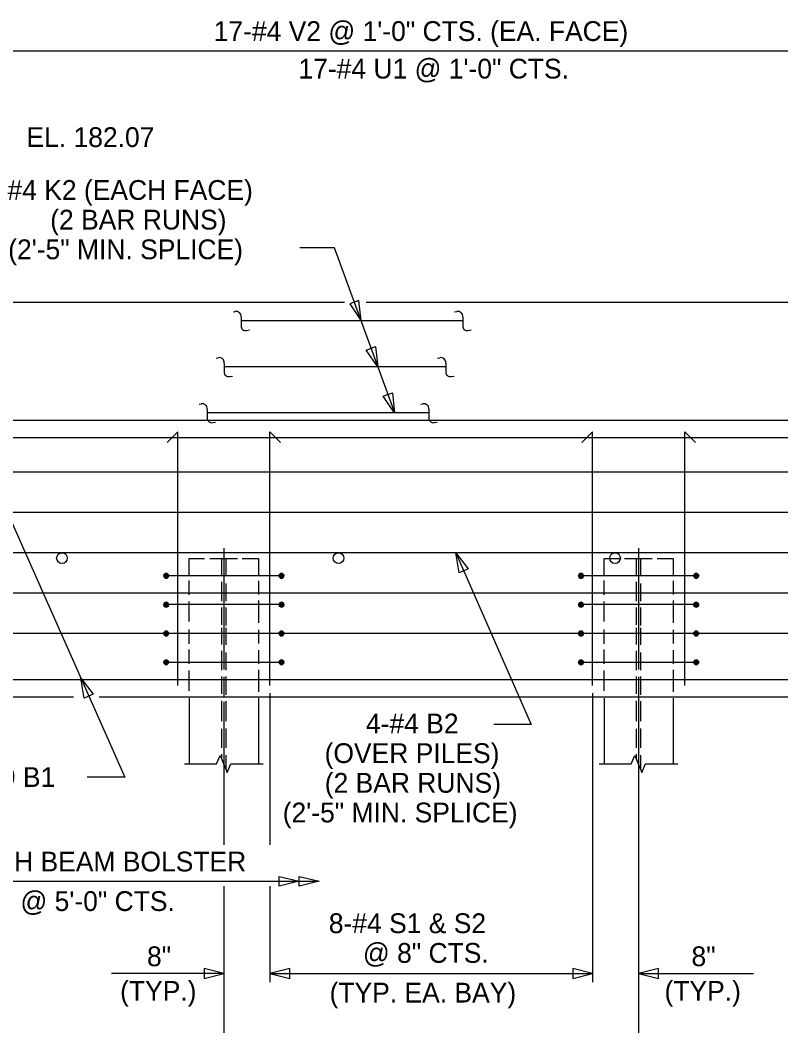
# Model space of a CAD drawing. Extents: x -41 to 191, y -168 to 6.
# Drawn here: x 132.62 to 143.62, y -41 to -26.46 of the extents above; entities that cross this region are included whole.
import ezdxf

# ---------------------------------------------------------------- set-up
doc = ezdxf.new("R2010")
doc.units = 0
for name, color, linetype in [('Arrowhead Terminators CELL', 7, 'Continuous'), ('Dimension Lines', 7, 'Continuous'), ('Mis Object Lines', 7, 'Continuous'), ('Rebar Lines', 7, 'Continuous'), ('Rebar Lines CELL', 7, 'Continuous'), ('Text', 7, 'Continuous')]:
    doc.layers.add(name, color=color, linetype=linetype)

msp = doc.modelspace()

# ---------------------------------------------------------------- linework, layer by layer
at = {"layer": 'Arrowhead Terminators CELL'}
for p, q in [((135.699, -30.684), (135.73, -30.678)), ((135.699, -30.684), (135.73, -30.678)), ((138.904, -30.684), (138.935, -30.678)), ((135.817, -30.757), (135.817, -30.883)), ((135.817, -30.757), (135.817, -30.883)), ((139.022, -30.757), (139.022, -30.883)), ((135.895, -30.95), (135.936, -30.944)), ((135.895, -30.95), (135.936, -30.944)), ((139.1, -30.95), (139.142, -30.944)), ((135.454, -31.35), (135.485, -31.345)), ((135.454, -31.35), (135.485, -31.345)), ((138.659, -31.35), (138.69, -31.345)), ((138.659, -31.35), (138.69, -31.345)), ((135.572, -31.423), (135.572, -31.55)), ((135.572, -31.423), (135.572, -31.55)), ((138.777, -31.423), (138.777, -31.55)), ((138.777, -31.423), (138.777, -31.55)), ((135.65, -31.616), (135.692, -31.611)), ((135.65, -31.616), (135.692, -31.611)), ((138.855, -31.616), (138.897, -31.611)), ((138.855, -31.616), (138.897, -31.611)), ((135.209, -32.017), (135.24, -32.012)), ((135.209, -32.017), (135.24, -32.012)), ((135.327, -32.09), (135.327, -32.216)), ((135.327, -32.09), (135.327, -32.216)), ((138.414, -32.017), (138.445, -32.012)), ((138.414, -32.017), (138.445, -32.012)), ((138.532, -32.09), (138.532, -32.216)), ((138.532, -32.09), (138.532, -32.216)), ((135.405, -32.283), (135.447, -32.278)), ((135.405, -32.283), (135.447, -32.278)), ((138.61, -32.283), (138.652, -32.278)), ((138.61, -32.283), (138.652, -32.278))]:
    msp.add_line(p, q, dxfattribs=at)
for points in [[(137.553, -30.811), (137.521, -30.518), (137.387, -30.567)], [(137.792, -31.478), (137.626, -31.234), (137.76, -31.184)], [(138.037, -32.144), (137.871, -31.9), (138.005, -31.851)], [(138.922, -34.165), (139.103, -34.398), (138.971, -34.456)], [(133.496, -35.978), (133.677, -36.211), (133.546, -36.269)], [(136.655, -38.915), (136.366, -38.987), (136.366, -38.843)], [(136.944, -38.915), (136.655, -38.987), (136.655, -38.843)], [(135.566, -40.249), (135.28, -40.177), (135.28, -40.32)], [(136.233, -40.249), (136.519, -40.32), (136.519, -40.177)], [(140.9, -40.249), (140.613, -40.177), (140.613, -40.32)], [(141.566, -40.249), (141.853, -40.32), (141.853, -40.177)]]:
    msp.add_lwpolyline(points, close=True, dxfattribs=at)
for centre, radius, start, end in [((135.746, -30.748), 0.0712, 353.437, 103.2358), ((135.746, -30.748), 0.0712, 353.437, 103.2358), ((138.951, -30.748), 0.0712, 353.437, 103.2358), ((135.879, -30.888), 0.0632, 175.8818, 284.1674), ((135.879, -30.888), 0.0632, 175.8818, 284.1674), ((139.085, -30.888), 0.0632, 175.8818, 284.1674), ((135.501, -31.415), 0.0712, 353.437, 103.2358), ((135.501, -31.415), 0.0712, 353.437, 103.2358), ((138.706, -31.415), 0.0712, 353.437, 103.2358), ((138.706, -31.415), 0.0712, 353.437, 103.2358), ((135.634, -31.555), 0.0632, 175.8818, 284.1674), ((135.634, -31.555), 0.0632, 175.8818, 284.1674), ((138.84, -31.555), 0.0632, 175.8818, 284.1674), ((138.84, -31.555), 0.0632, 175.8818, 284.1674), ((135.256, -32.082), 0.0712, 353.437, 103.2358), ((135.256, -32.082), 0.0712, 353.437, 103.2358), ((138.461, -32.082), 0.0712, 353.437, 103.2358), ((138.461, -32.082), 0.0712, 353.437, 103.2358), ((135.389, -32.221), 0.0632, 175.8818, 284.1674), ((135.389, -32.221), 0.0632, 175.8818, 284.1674), ((138.595, -32.221), 0.0632, 175.8818, 284.1674), ((138.595, -32.221), 0.0632, 175.8818, 284.1674)]:
    msp.add_arc(centre, radius, start, end, dxfattribs=at)
at = {"layer": 'Dimension Lines'}
for p, q in [((131.375, -26.909), (147.448, -26.909)), ((136.233, -36.195), (136.233, -38.388)), ((140.9, -36.195), (140.9, -40.374)), ((141.566, -36.249), (141.566, -42.558)), ((135.566, -37.524), (135.566, -38.388)), ((131.03, -38.915), (136.944, -38.915)), ((135.566, -38.987), (135.566, -42.873)), ((136.233, -38.987), (136.233, -40.374)), ((135.566, -40.249), (133.941, -40.249)), ((136.233, -40.249), (140.9, -40.249)), ((141.566, -40.249), (143.228, -40.249))]:
    msp.add_line(p, q, dxfattribs=at)
for points in [[(138.042, -32.144), (137.166, -29.758), (136.666, -29.758)], [(131.952, -32.5), (134.132, -37.41), (133.591, -37.41)], [(138.922, -34.165), (140.014, -36.648), (139.473, -36.648)]]:
    msp.add_lwpolyline(points, dxfattribs=at)
at = {"layer": 'Mis Object Lines'}
for p, q in [((130.841, -30.54), (137.314, -30.54)), ((137.623, -30.54), (164.491, -30.54)), ((131.167, -32.249), (147.948, -32.249)), ((126.948, -36.249), (133.392, -36.249)), ((133.764, -36.249), (168.185, -36.249))]:
    msp.add_line(p, q, dxfattribs=at)
at = {"layer": 'Rebar Lines'}
for p, q in [((139.023, -30.811), (135.818, -30.811)), ((138.778, -31.478), (135.573, -31.478)), ((138.534, -32.144), (135.328, -32.144)), ((134.9, -32.415), (134.746, -32.569)), ((134.9, -36.082), (134.9, -32.415)), ((136.233, -32.415), (136.387, -32.569)), ((136.233, -36.082), (136.233, -32.415)), ((140.9, -32.415), (140.746, -32.569)), ((140.9, -36.082), (140.9, -32.415)), ((142.233, -32.415), (142.387, -32.569)), ((142.233, -36.082), (142.233, -32.415)), ((127.69, -32.5), (166.732, -32.5)), ((149.156, -32.999), (127.115, -32.999)), ((149.156, -33.582), (127.115, -33.582)), ((149.156, -34.165), (127.115, -34.165)), ((135.566, -34.097), (135.566, -35.854)), ((141.566, -34.097), (141.566, -35.854)), ((135.535, -34.491), (135.535, -34.249)), ((135.598, -34.497), (135.598, -34.249)), ((141.535, -34.491), (141.535, -34.249)), ((141.598, -34.497), (141.598, -34.249)), ((135.535, -34.863), (135.535, -34.584)), ((141.535, -34.863), (141.535, -34.584)), ((149.156, -34.749), (127.115, -34.749)), ((135.598, -34.863), (135.598, -34.607)), ((141.598, -34.863), (141.598, -34.607)), ((135.535, -35.206), (135.535, -34.956)), ((135.598, -35.217), (135.598, -34.956)), ((141.535, -35.206), (141.535, -34.956)), ((141.598, -35.217), (141.598, -34.956)), ((149.156, -35.332), (127.115, -35.332)), ((135.535, -35.491), (135.535, -35.249)), ((135.598, -35.497), (135.598, -35.249)), ((141.535, -35.491), (141.535, -35.249)), ((141.598, -35.497), (141.598, -35.249)), ((135.535, -35.863), (135.535, -35.584)), ((135.598, -35.863), (135.598, -35.607)), ((141.535, -35.863), (141.535, -35.584)), ((141.598, -35.863), (141.598, -35.607)), ((127.69, -35.999), (166.825, -35.999)), ((135.535, -36.206), (135.535, -35.956)), ((135.566, -35.958), (135.566, -36.249)), ((135.598, -36.217), (135.598, -35.956)), ((141.535, -36.206), (141.535, -35.956)), ((141.566, -35.958), (141.566, -36.249)), ((141.598, -36.217), (141.598, -35.956)), ((135.066, -36.266), (135.066, -37.218)), ((135.535, -36.601), (135.535, -36.304)), ((135.566, -36.318), (135.566, -37.524)), ((135.598, -36.601), (135.598, -36.31)), ((136.067, -36.266), (136.067, -37.218)), ((141.066, -36.266), (141.066, -37.218)), ((141.535, -36.601), (141.535, -36.304)), ((141.566, -36.318), (141.566, -37.524)), ((141.598, -36.601), (141.598, -36.31)), ((142.067, -36.266), (142.067, -37.218)), ((135.535, -36.984), (135.535, -36.711)), ((135.598, -36.984), (135.598, -36.705)), ((141.535, -36.984), (141.535, -36.711)), ((141.598, -36.984), (141.598, -36.705)), ((135.535, -37.152), (135.535, -37.077)), ((141.535, -37.152), (141.535, -37.077)), ((135.598, -37.301), (135.598, -37.089)), ((141.598, -37.301), (141.598, -37.089))]:
    msp.add_line(p, q, dxfattribs=at)
for points in [[(135.066, -34.482), (135.066, -34.249), (135.289, -34.249)], [(135.364, -34.249), (135.764, -34.249)], [(135.833, -34.249), (136.066, -34.249), (136.066, -34.495)], [(141.066, -34.482), (141.066, -34.249), (141.289, -34.249)], [(141.364, -34.249), (141.764, -34.249)], [(141.833, -34.249), (142.066, -34.249), (142.066, -34.495)], [(135.066, -34.773), (135.066, -34.565)], [(136.066, -34.571), (136.066, -34.77)], [(141.066, -34.773), (141.066, -34.565)], [(142.066, -34.571), (142.066, -34.77)], [(135.066, -35.16), (135.066, -34.868)], [(136.066, -34.855), (136.066, -35.176)], [(141.066, -35.16), (141.066, -34.868)], [(142.066, -34.855), (142.066, -35.176)], [(135.066, -35.482), (135.066, -35.274)], [(136.066, -35.28), (136.066, -35.479)], [(141.066, -35.482), (141.066, -35.274)], [(142.066, -35.28), (142.066, -35.479)], [(135.066, -35.773), (135.066, -35.565)], [(136.066, -35.571), (136.066, -35.77)], [(141.066, -35.773), (141.066, -35.565)], [(142.066, -35.571), (142.066, -35.77)], [(135.066, -36.16), (135.066, -35.868)], [(136.066, -35.855), (136.066, -36.176)], [(141.066, -36.16), (141.066, -35.868)], [(142.066, -35.855), (142.066, -36.176)], [(134.996, -37.218), (135.458, -37.218), (135.513, -37.098), (135.615, -37.343), (135.667, -37.218), (136.133, -37.218)], [(140.996, -37.218), (141.458, -37.218), (141.513, -37.098), (141.615, -37.343), (141.667, -37.218), (142.133, -37.218)]]:
    msp.add_lwpolyline(points, dxfattribs=at)
at = {"layer": 'Rebar Lines CELL'}
for p, q in [((136.4, -34.499), (134.733, -34.499)), ((142.4, -34.499), (140.733, -34.499)), ((136.4, -34.915), (134.733, -34.915)), ((142.4, -34.915), (140.733, -34.915)), ((136.4, -35.332), (134.733, -35.332)), ((142.4, -35.332), (140.733, -35.332)), ((136.4, -35.749), (134.733, -35.749)), ((142.4, -35.749), (140.733, -35.749))]:
    msp.add_line(p, q, dxfattribs=at)
for points in [[(134.733, -34.463), (134.72, -34.466), (134.708, -34.474), (134.7, -34.485), (134.698, -34.499), (134.7, -34.512), (134.708, -34.523), (134.72, -34.531), (134.733, -34.534), (134.746, -34.531), (134.758, -34.523), (134.766, -34.512), (134.768, -34.499), (134.766, -34.485), (134.758, -34.474), (134.747, -34.466), (134.733, -34.463), (134.733, -34.499), (134.733, -34.534), (134.72, -34.531), (134.733, -34.499), (134.708, -34.523), (134.7, -34.512), (134.733, -34.499), (134.698, -34.499), (134.7, -34.485), (134.733, -34.499), (134.708, -34.474), (134.72, -34.466), (134.733, -34.499), (134.747, -34.466), (134.758, -34.474), (134.733, -34.499), (134.766, -34.485), (134.768, -34.499), (134.733, -34.499), (134.766, -34.512), (134.758, -34.523), (134.733, -34.499), (134.746, -34.531)], [(136.4, -34.463), (136.386, -34.466), (136.375, -34.474), (136.367, -34.485), (136.365, -34.499), (136.367, -34.512), (136.375, -34.523), (136.386, -34.531), (136.4, -34.534), (136.413, -34.531), (136.425, -34.523), (136.432, -34.512), (136.435, -34.499), (136.432, -34.485), (136.425, -34.474), (136.413, -34.466), (136.4, -34.463), (136.4, -34.499), (136.4, -34.534), (136.386, -34.531), (136.4, -34.499), (136.375, -34.523), (136.367, -34.512), (136.4, -34.499), (136.365, -34.499), (136.367, -34.485), (136.4, -34.499), (136.375, -34.474), (136.386, -34.466), (136.4, -34.499), (136.413, -34.466), (136.425, -34.474), (136.4, -34.499), (136.432, -34.485), (136.435, -34.499), (136.4, -34.499), (136.432, -34.512), (136.425, -34.523), (136.4, -34.499), (136.413, -34.531)], [(140.733, -34.463), (140.72, -34.466), (140.708, -34.474), (140.7, -34.485), (140.698, -34.499), (140.7, -34.512), (140.708, -34.523), (140.72, -34.531), (140.733, -34.534), (140.746, -34.531), (140.758, -34.523), (140.766, -34.512), (140.768, -34.499), (140.766, -34.485), (140.758, -34.474), (140.747, -34.466), (140.733, -34.463), (140.733, -34.499), (140.733, -34.534), (140.72, -34.531), (140.733, -34.499), (140.708, -34.523), (140.7, -34.512), (140.733, -34.499), (140.698, -34.499), (140.7, -34.485), (140.733, -34.499), (140.708, -34.474), (140.72, -34.466), (140.733, -34.499), (140.747, -34.466), (140.758, -34.474), (140.733, -34.499), (140.766, -34.485), (140.768, -34.499), (140.733, -34.499), (140.766, -34.512), (140.758, -34.523), (140.733, -34.499), (140.746, -34.531)], [(142.4, -34.463), (142.386, -34.466), (142.375, -34.474), (142.367, -34.485), (142.365, -34.499), (142.367, -34.512), (142.375, -34.523), (142.386, -34.531), (142.4, -34.534), (142.413, -34.531), (142.425, -34.523), (142.432, -34.512), (142.435, -34.499), (142.432, -34.485), (142.425, -34.474), (142.413, -34.466), (142.4, -34.463), (142.4, -34.499), (142.4, -34.534), (142.386, -34.531), (142.4, -34.499), (142.375, -34.523), (142.367, -34.512), (142.4, -34.499), (142.365, -34.499), (142.367, -34.485), (142.4, -34.499), (142.375, -34.474), (142.386, -34.466), (142.4, -34.499), (142.413, -34.466), (142.425, -34.474), (142.4, -34.499), (142.432, -34.485), (142.435, -34.499), (142.4, -34.499), (142.432, -34.512), (142.425, -34.523), (142.4, -34.499), (142.413, -34.531)], [(134.733, -34.88), (134.72, -34.883), (134.708, -34.89), (134.7, -34.902), (134.698, -34.915), (134.7, -34.929), (134.708, -34.94), (134.72, -34.948), (134.733, -34.95), (134.746, -34.948), (134.758, -34.94), (134.766, -34.929), (134.768, -34.915), (134.766, -34.902), (134.758, -34.89), (134.747, -34.883), (134.733, -34.88), (134.733, -34.915), (134.733, -34.95), (134.72, -34.948), (134.733, -34.915), (134.708, -34.94), (134.7, -34.929), (134.733, -34.915), (134.698, -34.915), (134.7, -34.902), (134.733, -34.915), (134.708, -34.89), (134.72, -34.883), (134.733, -34.915), (134.747, -34.883), (134.758, -34.89), (134.733, -34.915), (134.766, -34.902), (134.768, -34.915), (134.733, -34.915), (134.766, -34.929), (134.758, -34.94), (134.733, -34.915), (134.746, -34.948)], [(136.4, -34.88), (136.386, -34.883), (136.375, -34.89), (136.367, -34.902), (136.365, -34.915), (136.367, -34.929), (136.375, -34.94), (136.386, -34.948), (136.4, -34.95), (136.413, -34.948), (136.425, -34.94), (136.432, -34.929), (136.435, -34.915), (136.432, -34.902), (136.425, -34.89), (136.413, -34.883), (136.4, -34.88), (136.4, -34.915), (136.4, -34.95), (136.386, -34.948), (136.4, -34.915), (136.375, -34.94), (136.367, -34.929), (136.4, -34.915), (136.365, -34.915), (136.367, -34.902), (136.4, -34.915), (136.375, -34.89), (136.386, -34.883), (136.4, -34.915), (136.413, -34.883), (136.425, -34.89), (136.4, -34.915), (136.432, -34.902), (136.435, -34.915), (136.4, -34.915), (136.432, -34.929), (136.425, -34.94), (136.4, -34.915), (136.413, -34.948)], [(140.733, -34.88), (140.72, -34.883), (140.708, -34.89), (140.7, -34.902), (140.698, -34.915), (140.7, -34.929), (140.708, -34.94), (140.72, -34.948), (140.733, -34.95), (140.746, -34.948), (140.758, -34.94), (140.766, -34.929), (140.768, -34.915), (140.766, -34.902), (140.758, -34.89), (140.747, -34.883), (140.733, -34.88), (140.733, -34.915), (140.733, -34.95), (140.72, -34.948), (140.733, -34.915), (140.708, -34.94), (140.7, -34.929), (140.733, -34.915), (140.698, -34.915), (140.7, -34.902), (140.733, -34.915), (140.708, -34.89), (140.72, -34.883), (140.733, -34.915), (140.747, -34.883), (140.758, -34.89), (140.733, -34.915), (140.766, -34.902), (140.768, -34.915), (140.733, -34.915), (140.766, -34.929), (140.758, -34.94), (140.733, -34.915), (140.746, -34.948)], [(142.4, -34.88), (142.386, -34.883), (142.375, -34.89), (142.367, -34.902), (142.365, -34.915), (142.367, -34.929), (142.375, -34.94), (142.386, -34.948), (142.4, -34.95), (142.413, -34.948), (142.425, -34.94), (142.432, -34.929), (142.435, -34.915), (142.432, -34.902), (142.425, -34.89), (142.413, -34.883), (142.4, -34.88), (142.4, -34.915), (142.4, -34.95), (142.386, -34.948), (142.4, -34.915), (142.375, -34.94), (142.367, -34.929), (142.4, -34.915), (142.365, -34.915), (142.367, -34.902), (142.4, -34.915), (142.375, -34.89), (142.386, -34.883), (142.4, -34.915), (142.413, -34.883), (142.425, -34.89), (142.4, -34.915), (142.432, -34.902), (142.435, -34.915), (142.4, -34.915), (142.432, -34.929), (142.425, -34.94), (142.4, -34.915), (142.413, -34.948)], [(134.733, -35.297), (134.72, -35.299), (134.708, -35.307), (134.7, -35.318), (134.698, -35.332), (134.7, -35.345), (134.708, -35.357), (134.72, -35.364), (134.733, -35.367), (134.746, -35.364), (134.758, -35.357), (134.766, -35.345), (134.768, -35.332), (134.766, -35.318), (134.758, -35.307), (134.747, -35.299), (134.733, -35.297), (134.733, -35.332), (134.733, -35.367), (134.72, -35.364), (134.733, -35.332), (134.708, -35.357), (134.7, -35.345), (134.733, -35.332), (134.698, -35.332), (134.7, -35.318), (134.733, -35.332), (134.708, -35.307), (134.72, -35.299), (134.733, -35.332), (134.747, -35.299), (134.758, -35.307), (134.733, -35.332), (134.766, -35.318), (134.768, -35.332), (134.733, -35.332), (134.766, -35.345), (134.758, -35.357), (134.733, -35.332), (134.746, -35.364)], [(136.4, -35.297), (136.386, -35.299), (136.375, -35.307), (136.367, -35.318), (136.365, -35.332), (136.367, -35.345), (136.375, -35.357), (136.386, -35.364), (136.4, -35.367), (136.413, -35.364), (136.425, -35.357), (136.432, -35.345), (136.435, -35.332), (136.432, -35.318), (136.425, -35.307), (136.413, -35.299), (136.4, -35.297), (136.4, -35.332), (136.4, -35.367), (136.386, -35.364), (136.4, -35.332), (136.375, -35.357), (136.367, -35.345), (136.4, -35.332), (136.365, -35.332), (136.367, -35.318), (136.4, -35.332), (136.375, -35.307), (136.386, -35.299), (136.4, -35.332), (136.413, -35.299), (136.425, -35.307), (136.4, -35.332), (136.432, -35.318), (136.435, -35.332), (136.4, -35.332), (136.432, -35.345), (136.425, -35.357), (136.4, -35.332), (136.413, -35.364)], [(140.733, -35.297), (140.72, -35.299), (140.708, -35.307), (140.7, -35.318), (140.698, -35.332), (140.7, -35.345), (140.708, -35.357), (140.72, -35.364), (140.733, -35.367), (140.746, -35.364), (140.758, -35.357), (140.766, -35.345), (140.768, -35.332), (140.766, -35.318), (140.758, -35.307), (140.747, -35.299), (140.733, -35.297), (140.733, -35.332), (140.733, -35.367), (140.72, -35.364), (140.733, -35.332), (140.708, -35.357), (140.7, -35.345), (140.733, -35.332), (140.698, -35.332), (140.7, -35.318), (140.733, -35.332), (140.708, -35.307), (140.72, -35.299), (140.733, -35.332), (140.747, -35.299), (140.758, -35.307), (140.733, -35.332), (140.766, -35.318), (140.768, -35.332), (140.733, -35.332), (140.766, -35.345), (140.758, -35.357), (140.733, -35.332), (140.746, -35.364)], [(142.4, -35.297), (142.386, -35.299), (142.375, -35.307), (142.367, -35.318), (142.365, -35.332), (142.367, -35.345), (142.375, -35.357), (142.386, -35.364), (142.4, -35.367), (142.413, -35.364), (142.425, -35.357), (142.432, -35.345), (142.435, -35.332), (142.432, -35.318), (142.425, -35.307), (142.413, -35.299), (142.4, -35.297), (142.4, -35.332), (142.4, -35.367), (142.386, -35.364), (142.4, -35.332), (142.375, -35.357), (142.367, -35.345), (142.4, -35.332), (142.365, -35.332), (142.367, -35.318), (142.4, -35.332), (142.375, -35.307), (142.386, -35.299), (142.4, -35.332), (142.413, -35.299), (142.425, -35.307), (142.4, -35.332), (142.432, -35.318), (142.435, -35.332), (142.4, -35.332), (142.432, -35.345), (142.425, -35.357), (142.4, -35.332), (142.413, -35.364)], [(134.733, -35.713), (134.72, -35.716), (134.708, -35.724), (134.7, -35.735), (134.698, -35.749), (134.7, -35.762), (134.708, -35.773), (134.72, -35.781), (134.733, -35.784), (134.746, -35.781), (134.758, -35.773), (134.766, -35.762), (134.768, -35.749), (134.766, -35.735), (134.758, -35.724), (134.747, -35.716), (134.733, -35.713), (134.733, -35.749), (134.733, -35.784), (134.72, -35.781), (134.733, -35.749), (134.708, -35.773), (134.7, -35.762), (134.733, -35.749), (134.698, -35.749), (134.7, -35.735), (134.733, -35.749), (134.708, -35.724), (134.72, -35.716), (134.733, -35.749), (134.747, -35.716), (134.758, -35.724), (134.733, -35.749), (134.766, -35.735), (134.768, -35.749), (134.733, -35.749), (134.766, -35.762), (134.758, -35.773), (134.733, -35.749), (134.746, -35.781)], [(136.4, -35.713), (136.386, -35.716), (136.375, -35.724), (136.367, -35.735), (136.365, -35.749), (136.367, -35.762), (136.375, -35.773), (136.386, -35.781), (136.4, -35.784), (136.413, -35.781), (136.425, -35.773), (136.432, -35.762), (136.435, -35.749), (136.432, -35.735), (136.425, -35.724), (136.413, -35.716), (136.4, -35.713), (136.4, -35.749), (136.4, -35.784), (136.386, -35.781), (136.4, -35.749), (136.375, -35.773), (136.367, -35.762), (136.4, -35.749), (136.365, -35.749), (136.367, -35.735), (136.4, -35.749), (136.375, -35.724), (136.386, -35.716), (136.4, -35.749), (136.413, -35.716), (136.425, -35.724), (136.4, -35.749), (136.432, -35.735), (136.435, -35.749), (136.4, -35.749), (136.432, -35.762), (136.425, -35.773), (136.4, -35.749), (136.413, -35.781)], [(140.733, -35.713), (140.72, -35.716), (140.708, -35.724), (140.7, -35.735), (140.698, -35.749), (140.7, -35.762), (140.708, -35.773), (140.72, -35.781), (140.733, -35.784), (140.746, -35.781), (140.758, -35.773), (140.766, -35.762), (140.768, -35.749), (140.766, -35.735), (140.758, -35.724), (140.747, -35.716), (140.733, -35.713), (140.733, -35.749), (140.733, -35.784), (140.72, -35.781), (140.733, -35.749), (140.708, -35.773), (140.7, -35.762), (140.733, -35.749), (140.698, -35.749), (140.7, -35.735), (140.733, -35.749), (140.708, -35.724), (140.72, -35.716), (140.733, -35.749), (140.747, -35.716), (140.758, -35.724), (140.733, -35.749), (140.766, -35.735), (140.768, -35.749), (140.733, -35.749), (140.766, -35.762), (140.758, -35.773), (140.733, -35.749), (140.746, -35.781)], [(142.4, -35.713), (142.386, -35.716), (142.375, -35.724), (142.367, -35.735), (142.365, -35.749), (142.367, -35.762), (142.375, -35.773), (142.386, -35.781), (142.4, -35.784), (142.413, -35.781), (142.425, -35.773), (142.432, -35.762), (142.435, -35.749), (142.432, -35.735), (142.425, -35.724), (142.413, -35.716), (142.4, -35.713), (142.4, -35.749), (142.4, -35.784), (142.386, -35.781), (142.4, -35.749), (142.375, -35.773), (142.367, -35.762), (142.4, -35.749), (142.365, -35.749), (142.367, -35.735), (142.4, -35.749), (142.375, -35.724), (142.386, -35.716), (142.4, -35.749), (142.413, -35.716), (142.425, -35.724), (142.4, -35.749), (142.432, -35.735), (142.435, -35.749), (142.4, -35.749), (142.432, -35.762), (142.425, -35.773), (142.4, -35.749), (142.413, -35.781)]]:
    msp.add_lwpolyline(points, dxfattribs=at)
for centre in [(133.225, -34.242), (137.225, -34.242), (141.225, -34.242)]:
    msp.add_circle(centre, 0.0773, dxfattribs=at)

# ---------------------------------------------------------------- texts
at = {"layer": 'Text'}
for s, p in [('17-#4 V2 @ 1\'-0" CTS. (EA. FACE)', (135.42, -26.766)), ('17-#4 U1 @ 1\'-0" CTS.', (136.646, -27.309)), ('EL. 182.07', (132.712, -28.299)), ('#4 K2 (EACH FACE)', (132.437, -29.063)), ('(2 BAR RUNS)', (133.055, -29.492)), ('(2\'-5" MIN. SPLICE) ', (132.447, -29.921)), ('4-#4 B2', (137.622, -36.776)), ('(OVER PILES)', (137.024, -37.205)), ('4-#9 B1', (131.788, -37.551)), ('(2 BAR RUNS)', (137.026, -37.634)), ('(2\'-5" MIN. SPLICE)', (136.418, -38.063)), ('3" HIGH BEAM BOLSTER', (131.398, -38.772)), ('@ 5\'-0" CTS.', (132.624, -39.344)), ('8-#4 S1 & S2', (137.085, -39.664)), ('@ 8" CTS.', (137.578, -40.093)), ('8"', (134.455, -40.142)), ('8"', (142.331, -40.142)), ('(TYP.)', (134.066, -40.642)), ('(TYP. EA. BAY)', (137.096, -40.667)), ('(TYP.)', (141.941, -40.642))]:
    msp.add_text(s, height=0.286, dxfattribs=at).set_placement(p)

doc.saveas('drawing.dxf')
